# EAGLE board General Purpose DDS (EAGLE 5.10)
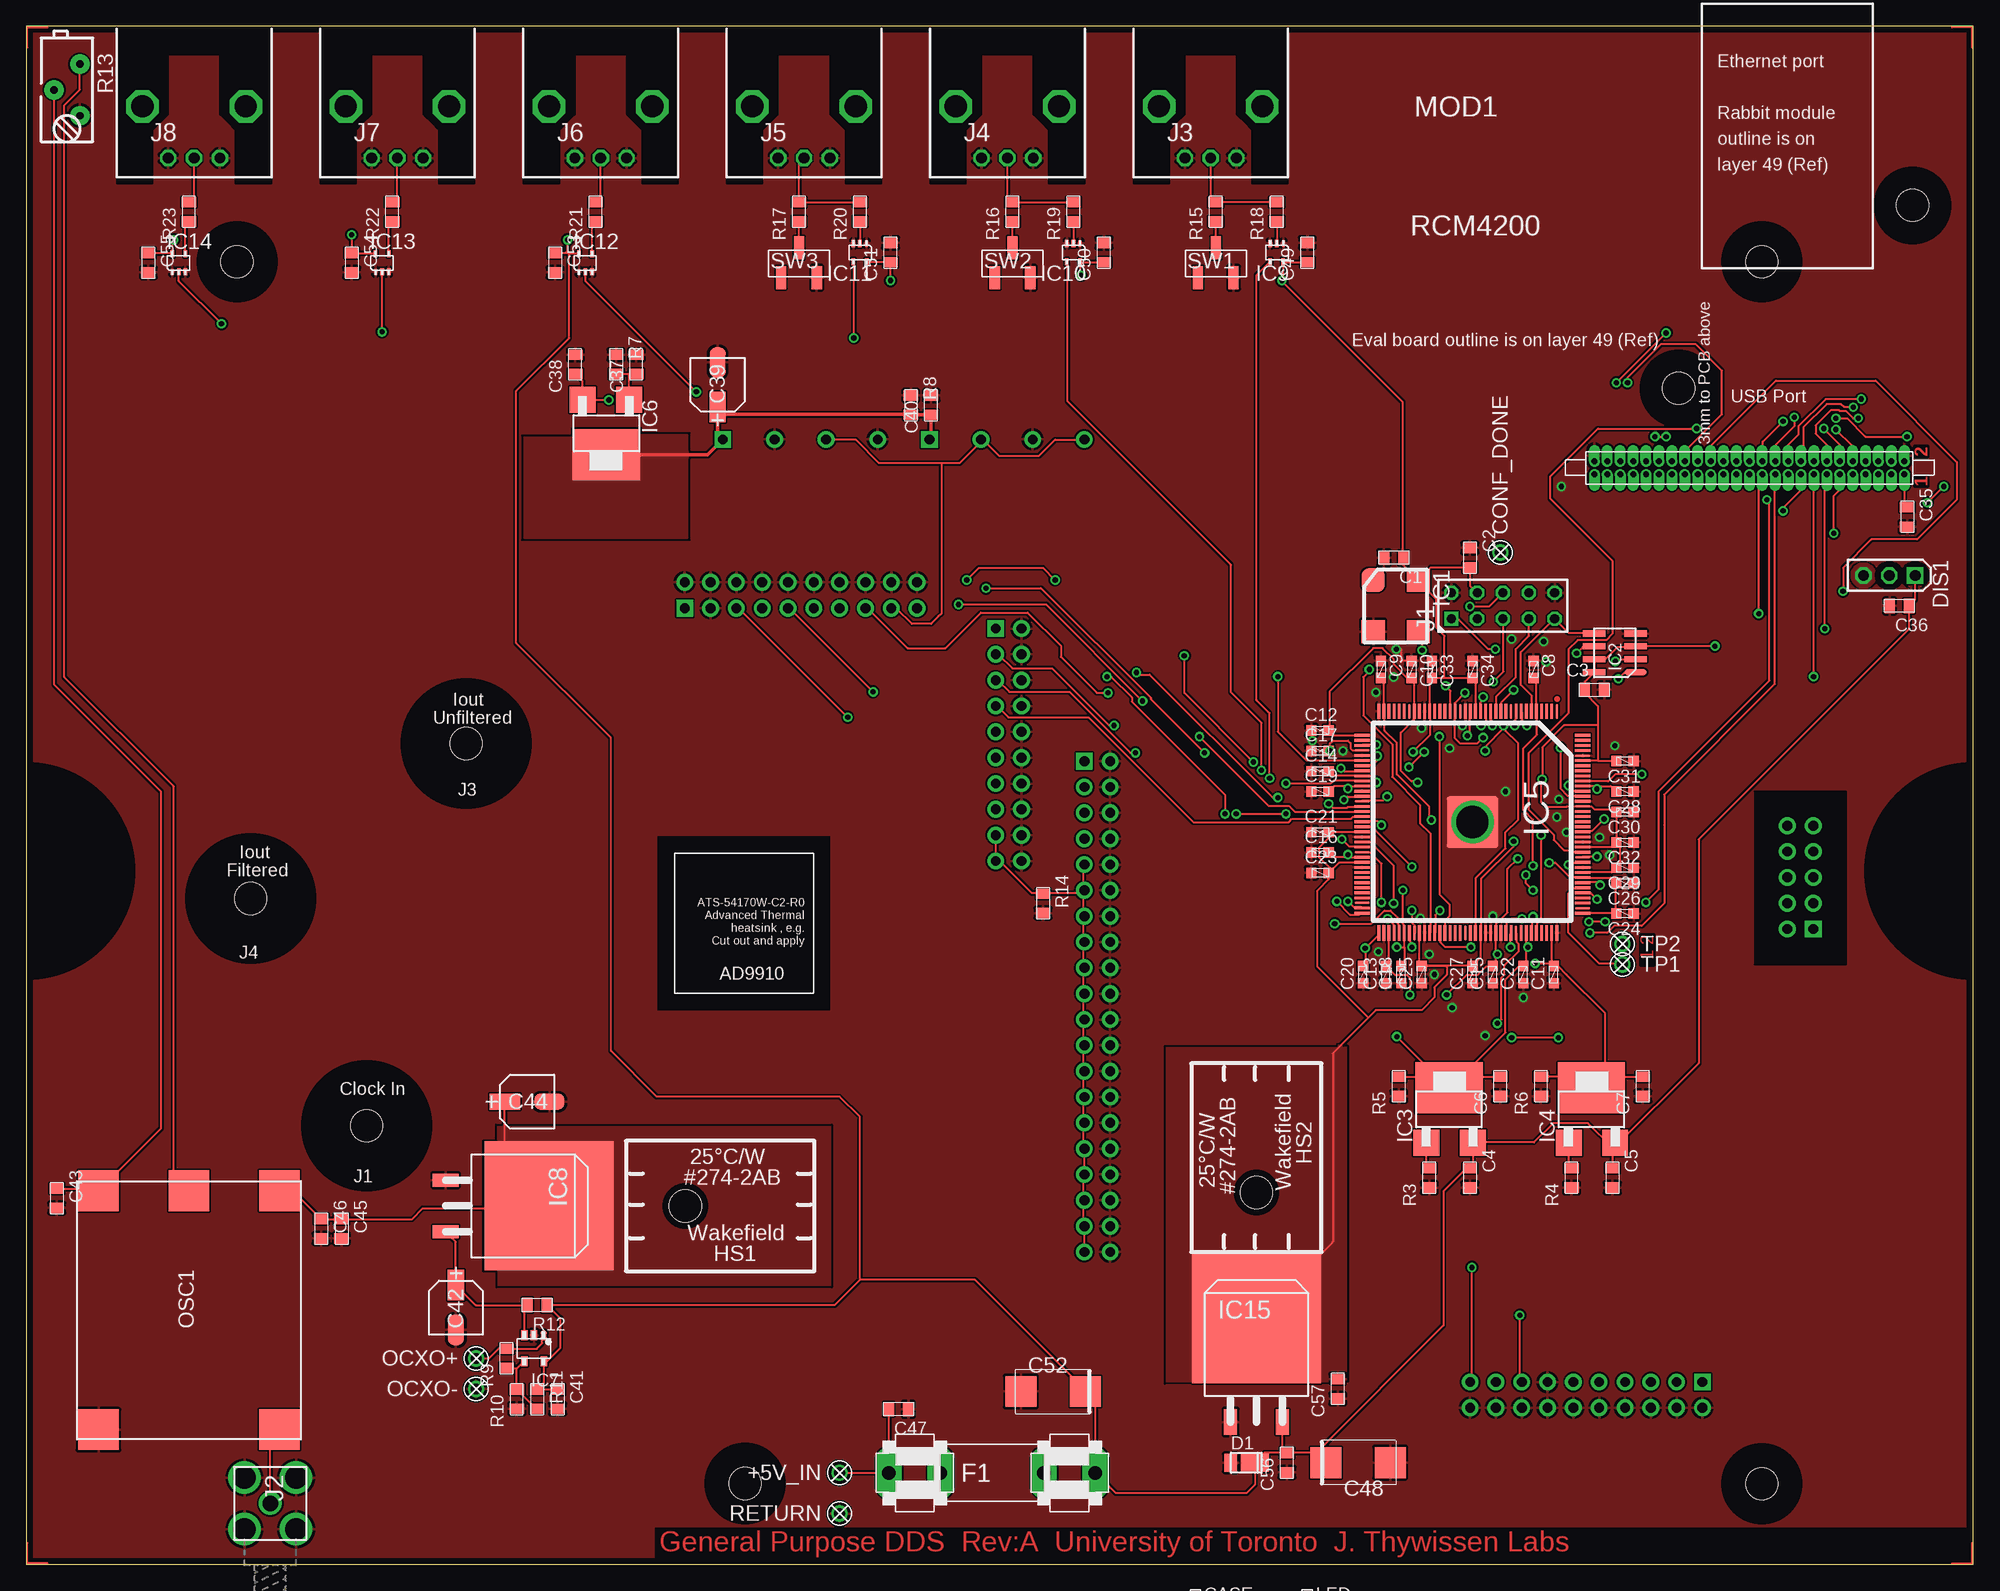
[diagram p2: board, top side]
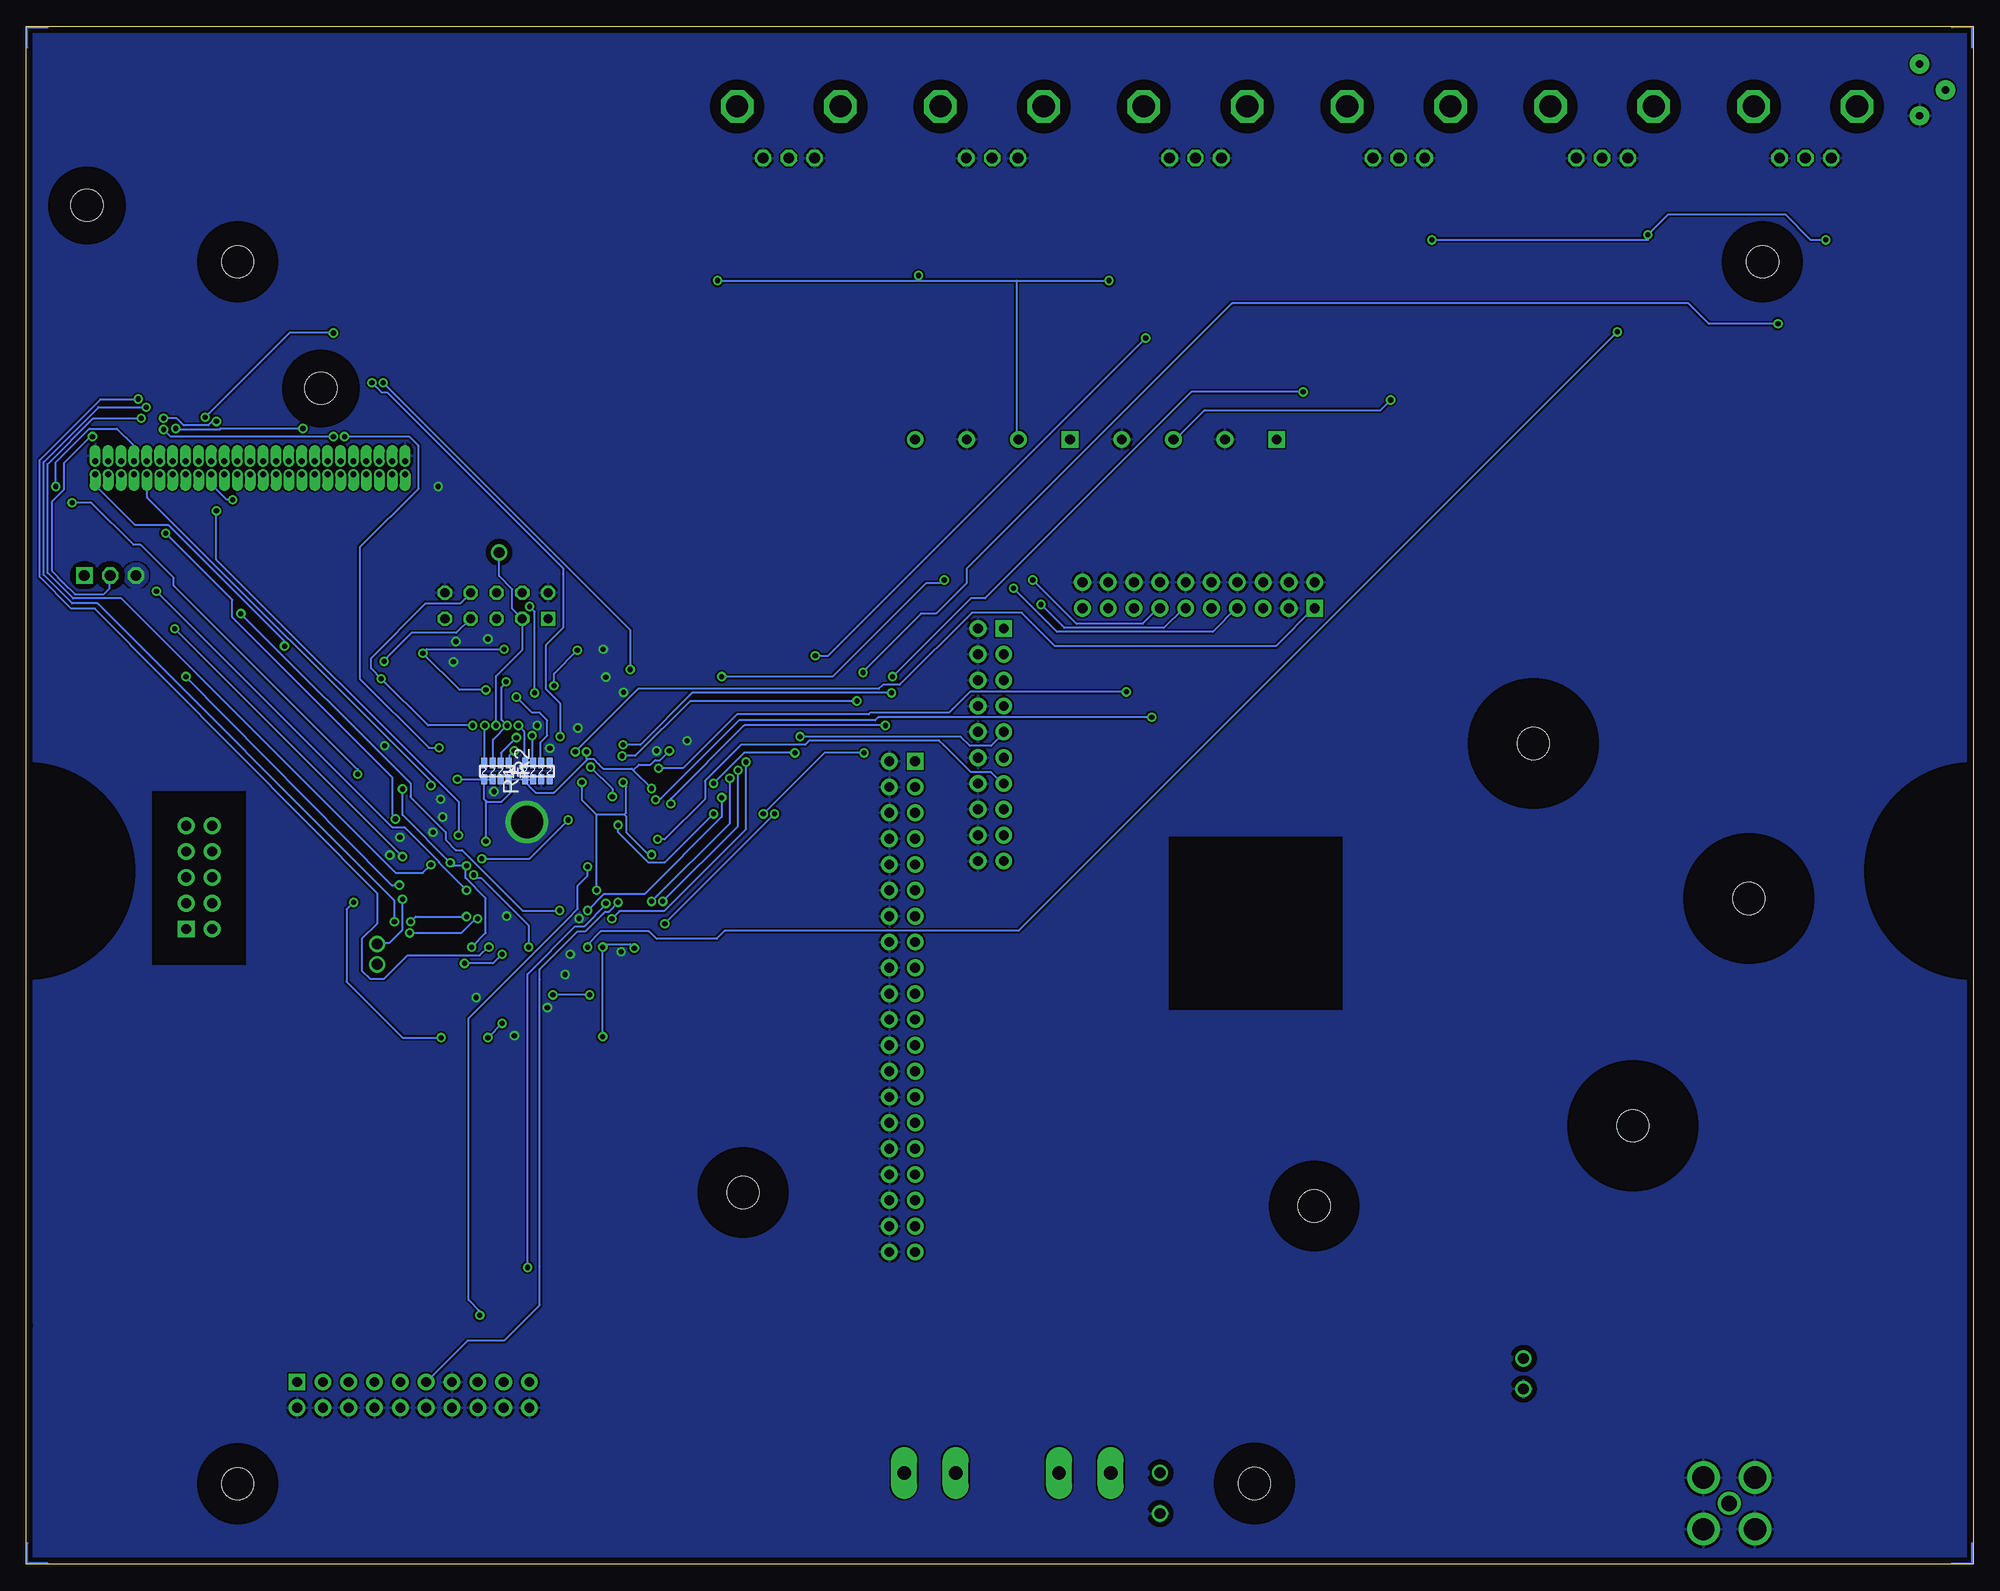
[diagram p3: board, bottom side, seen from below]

Size 191.5 x 151.25 mm. Coordinates in mm from the lower left corner, seen from the top.
Outline: 191.5,23.5 191.5,151.25 0,151.25 0,0 182,0 191.5,0 191.5,23.5
Copper layers (1+16): Top 0.035mm / dielectric 1.5mm / Bottom 0.035mm
Design rules "DRC standard check": minimum track width 7mil, minimum drill 20mil, track to track 7mil, track to pad 7mil, pad to pad 7mil, via to via 7mil, smd to smd 0mil, copper to edge 25mil, drill to drill 8mil, minimum pad ring 10mil, minimum via ring 8mil, stop-mask expansion 4mil, vias tented up to drill 0mil, thermal gap 10mil
Net classes: 0 default: width 0.178 mm, drill 0.508 mm, clearance 0.178 mm; 1 Power: width 0.356 mm, drill 0.711 mm, clearance 0.178 mm
Holes 3.17 mm at 20.71,128.09 170.72,128.1 170.72,7.94 70.71,7.96
tRestrict: area -10.7,57.5 to 10.7,78.9; area 180.8,57.5 to 202.2,78.9; area 16.9,124.3 to 24.5,131.9; area 166.9,124.3 to 174.5,131.9; area 166.9,4.1 to 174.5,11.7; area 66.9,4.1 to 74.5,11.8; 29 lines
bRestrict: area -10.7,57.5 to 10.7,78.9; area 180.8,57.5 to 202.2,78.9; area 16.9,124.3 to 24.5,131.9; area 166.9,124.3 to 174.5,131.9; area 166.9,4.1 to 174.5,11.7; area 66.9,4.1 to 74.5,11.8; 6 lines

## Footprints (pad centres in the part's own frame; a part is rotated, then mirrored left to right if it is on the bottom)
TP-0.042B = drill 1.067 round: TP 0,0
2012(0805) = smd 1.016 x 1.397: 1 -0.953,0; 2 0.953,0
1608(0603) = smd 1.016 x 1.016: 1 -0.85,0; 2 0.85,0
CAP:NIPPONCHEM_E61 = smd 3 x 1.6: NEG -2.2,0; POS 2.2,0
EIA-7343 = smd 3.048 x 3.048: + 3.175,0; - -3.175,0
ZENER:DFLZ_V_(1W) = smd 1.25 x 1.75: A -1.525,0 | smd 2.75 x 1.75: C 0.85,0
DDS:AD9910,EVALBOARD = drill 0.965 pad 1.651 square: P1.1 74.5,46.75; TB1.1 89.74,15.104; TB2.1 110.06,15.104; U5.1 113.806,31.701; U6.1 83.208,33.702; U8.1 2.807,63.254; U9.1 13.697,107.8 | drill 0.965 pad 1.651 round: P1.2 71.96,46.75; P1.3 74.5,49.29; P1.4 71.96,49.29; P1.5 74.5,51.83; P1.6 71.96,51.83; P1.7 74.5,54.37; P1.8 71.96,54.37; P1.9 74.5,56.91; P1.10 71.96,56.91; P1.11 74.5,59.45; P1.12 71.96,59.45; P1.13 74.5,61.99; P1.14 71.96,61.99; P1.15 74.5,64.53; P1.16 71.96,64.53; P1.17 74.5,67.07; P1.18 71.96,67.07; P1.19 74.5,69.61; P1.20 71.96,69.61; P1.21 74.5,72.15; P1.22 71.96,72.15; P1.23 74.5,74.69; P1.24 71.96,74.69; P1.25 74.5,77.23; P1.26 71.96,77.23; P1.27 74.5,79.77; P1.28 71.96,79.77; P1.29 74.5,82.31; P1.30 71.96,82.31; P1.31 74.5,84.85; P1.32 71.96,84.85; P1.33 74.5,87.39; P1.34 71.96,87.39; P1.35 74.5,89.93; P1.36 71.96,89.93; P1.37 74.5,92.47; P1.38 71.96,92.47; P1.39 74.5,95.01; P1.40 71.96,95.01; TB1.2 84.66,15.104; TB1.3 79.58,15.104; TB1.4 74.5,15.104; TB2.2 104.98,15.104; TB2.3 99.9,15.104; TB2.4 94.82,15.104; U5.2 113.806,29.161; U5.3 111.266,31.701; U5.4 111.266,29.161; U5.5 108.726,31.701; U5.6 108.726,29.161; U5.7 106.186,31.701; U5.8 106.186,29.161; U5.9 103.646,31.701; U5.10 103.646,29.161; U5.11 101.106,31.701; U5.12 101.106,29.161; U5.13 98.566,31.701; U5.14 98.566,29.161; U5.15 96.026,31.701; U5.16 96.026,29.161; U5.17 93.486,31.701; U5.18 93.486,29.161; U5.19 90.946,31.701; U5.20 90.946,29.161; U6.2 80.668,33.702; U6.3 83.208,36.242; U6.4 80.668,36.242; U6.5 83.208,38.782; U6.6 80.668,38.782; U6.7 83.208,41.322; U6.8 80.668,41.322; U6.9 83.208,43.862; U6.10 80.668,43.862; U6.11 83.208,46.402; U6.12 80.668,46.402; U6.13 83.208,48.942; U6.14 80.668,48.942; U6.15 83.208,51.482; U6.16 80.668,51.482; U6.17 83.208,54.022; U6.18 80.668,54.022; U6.19 83.208,56.562; U6.20 80.668,56.562; U8.2 5.347,63.254; U8.3 2.807,60.714; U8.4 5.347,60.714; U8.5 2.807,58.174; U8.6 5.347,58.174; U8.7 2.807,55.634; U8.8 5.347,55.634; U8.9 2.807,53.094; U8.10 5.347,53.094; U9.2 13.697,110.34; U9.3 16.237,107.8; U9.4 16.237,110.34; U9.5 18.777,107.8; U9.6 18.777,110.34; U9.7 21.317,107.8; U9.8 21.317,110.34; U9.9 23.857,107.8; U9.10 23.857,110.34; U9.11 26.397,107.8; U9.12 26.397,110.34; U9.13 28.937,107.8; U9.14 28.937,110.34; U9.15 31.477,107.8; U9.16 31.477,110.34; U9.17 34.017,107.8; U9.18 34.017,110.34; U9.19 36.557,107.8; U9.20 36.557,110.34 | hole 3.175: 135.3,45; 156.5,60.25; 145.1,82.6
DISPLAY:3WIRE = drill 1.067 octagon: COM 0,-2.54; RXD 0,0 | drill 1.067 square: VDD 0,2.54
FUSE = drill 1.321 pad 2.54 long: 1A -10.16,0; 1B -5.08,0; 2A 10.16,0; 2B 5.08,0
HEATSINK:274-2AB(WAKEFIELD,25C/W) = hole 3.175: 3.429,0
CSX750(CITIZEN_OSC) = smd 2.286 x 2.286: 1 -2.54,-1.27; 2 2.54,-1.27; 3 2.54,3.175; 4 -2.54,3.175
SOIC-8@1 = smd 0.6 x 2.2: 1 -1.27,-2.032; 2 0,-2.032; 3 1.27,-2.032; 4 2.54,-2.032; 5 2.54,2.032; 6 1.27,2.032; 7 0,2.032; 8 -1.27,2.032
SOT223(C) = smd 2.54 x 2.54: 1 -2.286,-2.54; 3 2.286,-2.54 | smd 6.6 x 5: 2 -0.05,2.87
EQFP144(TQFP_WITH_GROUND_PAD) = smd 1.5 x 0.27: 1 -10.89,8.29; 2 -10.89,7.79; 3 -10.89,7.29; 4 -10.89,6.79; 5 -10.89,6.29; 6 -10.89,5.79; 7 -10.89,5.29; 8 -10.89,4.79; 9 -10.89,4.29; 10 -10.89,3.79; 11 -10.89,3.29; 12 -10.89,2.79; 13 -10.89,2.29; 14 -10.89,1.79; 15 -10.89,1.29; 16 -10.89,0.79; 17 -10.89,0.29; 18 -10.89,-0.21; 19 -10.89,-0.71; 20 -10.89,-1.21; 21 -10.89,-1.71; 22 -10.89,-2.21; 23 -10.89,-2.71; 24 -10.89,-3.21; 25 -10.89,-3.71; 26 -10.89,-4.21; 27 -10.89,-4.71; 28 -10.89,-5.21; 29 -10.89,-5.71; 30 -10.89,-6.21; 31 -10.89,-6.71; 32 -10.89,-7.21; 33 -10.89,-7.71; 34 -10.89,-8.21; 35 -10.89,-8.71; 36 -10.89,-9.21; 73 10.91,-9.21; 74 10.91,-8.71; 75 10.91,-8.21; 76 10.91,-7.71; 77 10.91,-7.21; 78 10.91,-6.71; 79 10.91,-6.21; 80 10.91,-5.71; 81 10.91,-5.21; 82 10.91,-4.71; 83 10.91,-4.21; 84 10.91,-3.71; 85 10.91,-3.21; 86 10.91,-2.71; 87 10.91,-2.21; 88 10.91,-1.71; 89 10.91,-1.21; 90 10.91,-0.71; 91 10.91,-0.21; 92 10.91,0.29; 93 10.91,0.79; 94 10.91,1.29; 95 10.91,1.79; 96 10.91,2.29; 97 10.91,2.79; 98 10.91,3.29; 99 10.91,3.79; 100 10.91,4.29; 101 10.91,4.79; 102 10.91,5.29; 103 10.91,5.79; 104 10.91,6.29; 105 10.91,6.79; 106 10.91,7.29; 107 10.91,7.79; 108 10.91,8.29 | smd 0.27 x 1.5: 37 -8.54,-10.86; 38 -8.04,-10.86; 39 -7.54,-10.86; 40 -7.04,-10.86; 41 -6.54,-10.86; 42 -6.04,-10.86; 43 -5.54,-10.86; 44 -5.04,-10.86; 45 -4.54,-10.86; 46 -4.04,-10.86; 47 -3.54,-10.86; 48 -3.04,-10.86; 49 -2.54,-10.86; 50 -2.04,-10.86; 51 -1.54,-10.86; 52 -1.04,-10.86; 53 -0.54,-10.86; 54 -0.04,-10.86; 55 0.46,-10.86; 56 0.96,-10.86; 57 1.46,-10.86; 58 1.96,-10.86; 59 2.46,-10.86; 60 2.96,-10.86; 61 3.46,-10.86; 62 3.96,-10.86; 63 4.46,-10.86; 64 4.96,-10.86; 65 5.46,-10.86; 66 5.96,-10.86; 67 6.46,-10.86; 68 6.96,-10.86; 69 7.46,-10.86; 70 7.96,-10.86; 71 8.46,-10.86; 72 8.96,-10.86; 109 8.96,10.84; 110 8.46,10.84; 111 7.96,10.84; 112 7.46,10.84; 113 6.96,10.84; 114 6.46,10.84; 115 5.96,10.84; 116 5.46,10.84; 117 4.96,10.84; 118 4.46,10.84; 119 3.96,10.84; 120 3.46,10.84; 121 2.96,10.84; 122 2.46,10.84; 123 1.96,10.84; 124 1.46,10.84; 125 0.96,10.84; 126 0.46,10.84; 127 -0.04,10.84; 128 -0.54,10.84; 129 -1.04,10.84; 130 -1.54,10.84; 131 -2.04,10.84; 132 -2.54,10.84; 133 -3.04,10.84; 134 -3.54,10.84; 135 -4.04,10.84; 136 -4.54,10.84; 137 -5.04,10.84; 138 -5.54,10.84; 139 -6.04,10.84; 140 -6.54,10.84; 141 -7.04,10.84; 142 -7.54,10.84; 143 -8.04,10.84; 144 -8.54,10.84 | smd 5.08 x 5.08: PAD 0,0
SOT23-5 = smd 0.635 x 0.991: 1 -0.635,-1.27; 2 0.318,-1.27; 3 1.27,-1.27; 4 1.27,1.27; 5 -0.635,1.27
TO263 = smd 1.27 x 2.54: 1 -2.54,0; 3 2.54,0 | smd 12.7 x 12.7: 2 0,10.16
SOT353 = smd 0.35 x 0.7: 1 -0.65,-0.9; 2 0,-0.9; 3 0.65,-0.9; 4 0.65,0.9; 5 -0.65,0.9
CONN-2X5-BLASTER = drill 0.889 square: 1 0,5.08 | drill 0.889 octagon: 2 2.54,5.08; 3 0,2.54; 4 2.54,2.54; 5 0,0; 6 2.54,0; 7 0,-2.54; 8 2.54,-2.54; 9 0,-5.08; 10 2.54,-5.08
CONN:SMA1 = drill 2.184 round: COM1 -2.54,-2.54; COM2 -2.54,2.54; COM3 2.54,2.54; COM4 2.54,-2.54 | drill 1.511 round: CONDUCTOR 0,0
CONN-BNC-AMP-TYPE3HORIZ = drill 1.067 octagon: CONDUCTOR 0,-12.7; SHIELD1 -2.54,-12.7; SHIELD2 2.54,-12.7 | drill 2.184 octagon: P$1 -5.08,-7.62; P$2 5.08,-7.62
RABBIT_RCM42XX(THRU) = drill 0.584 pad 1.016 offset: 1 55.225,3.193; 2 55.225,4.463; 3 53.955,3.193; 4 53.955,4.463; 5 52.685,3.193; 6 52.685,4.463; 7 51.415,3.193; 8 51.415,4.463; 9 50.145,3.193; 10 50.145,4.463; 11 48.875,3.193; 12 48.875,4.463; 13 47.605,3.193; 14 47.605,4.463; 15 46.335,3.193; 16 46.335,4.463; 17 45.065,3.193; 18 45.065,4.463; 19 43.795,3.193; 20 43.795,4.463; 21 42.525,3.193; 22 42.525,4.463; 23 41.255,3.193; 24 41.255,4.463; 25 39.985,3.193; 26 39.985,4.463; 27 38.715,3.193; 28 38.715,4.463; 29 37.445,3.193; 30 37.445,4.463; 31 36.175,3.193; 32 36.175,4.463; 33 34.905,3.193; 34 34.905,4.463; 35 33.635,3.193; 36 33.635,4.463; 37 32.365,3.193; 38 32.365,4.463; 39 31.095,3.193; 40 31.095,4.463; 41 29.825,3.193; 42 29.825,4.463; 43 28.555,3.193; 44 28.555,4.463; 45 27.285,3.193; 46 27.285,4.463; 47 26.015,3.193; 48 26.015,4.463; 49 24.745,3.193; 50 24.745,4.463 | hole 3.175: 56.02,29.654; 33.02,11.654
OSCILLATOR:AOCJY(ABRACON-OCXO) = smd 4 x 4: COM 11.75,-8.9; CTRL -11.75,-8.9; OUT 11.75,8.9; VDD -11.75,8.9; VREF -11.75,0
PANASONIC_EXB-V8V(QUAD-R-PACK) = smd 1 x 0.59: 1A -0.8,1.2; 1B 0.8,1.2; 2A -0.8,0.4; 2B 0.8,0.4; 3A -0.8,-0.4; 3B 0.8,-0.4; 4A -0.8,-1.2; 4B 0.8,-1.2
BOURNS:3296Y = drill 0.711 pad 1.905 round: CCW 2.54,1.27; CW -2.54,1.27; W 0,-1.27
SWITCH:SPDT-DIP(COPAL) = smd 1 x 2.25: 1 -1.75,-1.475; 2 1.75,-1.475; COM 0,1.475

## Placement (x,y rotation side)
+5V_IN  [TP-0.042B]  80,9 180 top
C1  0.1uF  [2012(0805)]  134.5,99 180 top
C2  0.1uF  [2012(0805)]  142,99 270 top
C3  0.1uF  [2012(0805)]  154.25,86 0 top
C4  0.1uF  [2012(0805)]  142,38 270 top
C5  0.1uF  [2012(0805)]  156,38 270 top
C6  0.1uF  [2012(0805)]  145,47 90 top
C7  0.1uF  [2012(0805)]  159,47 90 top
C8  0.1uF  [1608(0603)]  148.25,88 270 top
C9  0.1uF  [1608(0603)]  133.25,88 270 top
C10  0.1uF  [1608(0603)]  136.25,88 270 top
C11  0.1uF  [1608(0603)]  150.25,58 90 top
C12  0.1uF  [1608(0603)]  127.25,82 0 top
C13  0.1uF  [1608(0603)]  133.75,58 90 top
C14  0.1uF  [1608(0603)]  127.25,78 0 top
C15  0.1uF  [1608(0603)]  144.25,58 90 top
C16  0.1uF  [1608(0603)]  127.25,70 0 top
C17  0.1uF  [1608(0603)]  127.25,80 0 top
C18  0.1uF  [1608(0603)]  135.25,58 90 top
C19  0.1uF  [1608(0603)]  127.25,76 0 top
C20  0.1uF  [1608(0603)]  131.5,58 90 top
C21  0.1uF  [1608(0603)]  127.25,72 0 top
C22  0.1uF  [1608(0603)]  147.25,58 90 top
C23  0.1uF  [1608(0603)]  127.25,68 0 top
C24  0.1uF  [1608(0603)]  157.25,64 180 top
C25  0.1uF  [1608(0603)]  137.25,58 90 top
C26  0.1uF  [1608(0603)]  157.25,67 180 top
C27  0.1uF  [1608(0603)]  142.25,58 90 top
C28  0.1uF  [1608(0603)]  157.25,76 180 top
C29  0.1uF  [1608(0603)]  157.25,68.5 180 top
C30  0.1uF  [1608(0603)]  157.25,74 180 top
C31  0.1uF  [1608(0603)]  157.25,79 180 top
C32  0.1uF  [1608(0603)]  157.25,71 180 top
C33  0.1uF  [1608(0603)]  138.25,88 270 top
C34  0.1uF  [1608(0603)]  142.25,88 270 top
C35  0.1uF  [2012(0805)]  185,103 270 top
C36  0.1uF  [2012(0805)]  184.25,94.25 180 top
C37  12pF  [2012(0805)]  60,118 90 top
C38  0.1uF  [2012(0805)]  54,118 90 top
C39  39uF  [CAP:NIPPONCHEM_E61]  68,116 270 top
C40  0.1uF  [2012(0805)]  89,114 90 top
C41  0.1uF  [2012(0805)]  52.25,16.25 270 top
C42  39uF  [CAP:NIPPONCHEM_E61]  42.25,25.25 90 top
C43  10nF  [2012(0805)]  3,36 270 top
C44  39uF  [CAP:NIPPONCHEM_E61]  49.25,45.5 180 top
C45  10nF  [2012(0805)]  31,33 270 top
C46  0.1uF  [2012(0805)]  29,33 270 top
C47  0.1uF  [2012(0805)]  85.8,15.26 180 top
C48  10uF  [EIA-7343]  131,10 180 top
C49  0.1uF  [2012(0805)]  126,129 90 top
C50  0.1uF  [2012(0805)]  106,129 90 top
C51  0.1uF  [2012(0805)]  85,129 90 top
C52  10uF  [EIA-7343]  101,17 0 top
C53  0.1uF  [2012(0805)]  52,128 270 top
C54  0.1uF  [2012(0805)]  32,128 270 top
C55  0.1uF  [2012(0805)]  12,128 270 top
C56  0.1uF  [2012(0805)]  124,10 90 top
C57  0.1uF  [2012(0805)]  129,17.25 90 top
CASE  1598D  [MISC]  115,-3 0 top
CBL1  A-MCU60005-R  [MISC]  not placed on the board
COAX  SMA-SMA coax  [MISC]  not placed on the board
COAX1  SMA-SMA coax  [MISC]  not placed on the board
CON1  555052-1  [MISC]  not placed on the board
CONF_DONE  [TP-0.042B]  145,99.5 90 top
CONN  SMA-SMA bulkhead  [MISC]  not placed on the board
D1  DFLZ5V6-7  [ZENER:DFLZ_V_(1W)]  120,10 0 top
DDS1  [DDS:AD9910,EVALBOARD]  178.57,125.73 180 top
DIS1  NHD-0216B3Z-FL-GBW  [DISPLAY:3WIRE]  183.25,97.25 270 top
F1  2A  [FUSE]  95,9 0 top
HS1  274-2AB  [HEATSINK:274-2AB(WAKEFIELD,25C/W)]  68.25,35.25 180 top
HS2  274-2AB  [HEATSINK:274-2AB(WAKEFIELD,25C/W)]  121,40 270 top
HTSNK  [MISC]  not placed on the board
IC1  100MHz  [CSX750(CITIZEN_OSC)]  133.75,94.25 270 top
IC2  EPCS4  [SOIC-8@1]  156.25,89 90 top
IC3  LT3080EST  [SOT223(C)]  140,44 0 top
IC4  LT3080EST  [SOT223(C)]  154,44 0 top
IC5  EP3C10E144C7  [EQFP144(TQFP_WITH_GROUND_PAD)]  142.25,73 270 top
IC6  LT3080EST  [SOT223(C)]  57,112 180 top
IC7  AD8605ART  [SOT23-5]  50.25,21.25 180 top
IC8  LM1086CS-3.3  [TO263]  41.25,35.25 270 top
IC9  NL17SZ125DFT2G  [SOT353]  123,129 180 top
IC10  NL17SZ125DFT2G  [SOT353]  103,129 180 top
IC11  NL17SZ125DFT2G  [SOT353]  82,129 180 top
IC12  NL17SZ125DFT2G  [SOT353]  55,128 0 top
IC13  NL17SZ125DFT2G  [SOT353]  35,128 0 top
IC14  NL17SZ125DFT2G  [SOT353]  15,128 0 top
IC15  LM1086CS-3.3  [TO263]  121,14 0 top
J1  [CONN-2X5-BLASTER]  145.25,93 90 top
J2  Amphenol 132134  [CONN:SMA1]  24,6 270 top
J3  227677-1  [CONN-BNC-AMP-TYPE3HORIZ]  116.5,151 0 top
J4  227677-1  [CONN-BNC-AMP-TYPE3HORIZ]  96.5,151 0 top
J5  227677-1  [CONN-BNC-AMP-TYPE3HORIZ]  76.5,151 0 top
J6  227677-1  [CONN-BNC-AMP-TYPE3HORIZ]  56.5,151 0 top
J7  227677-1  [CONN-BNC-AMP-TYPE3HORIZ]  36.5,151 0 top
J8  227677-1  [CONN-BNC-AMP-TYPE3HORIZ]  16.5,151 0 top
LED  OCXO LED  [MISC]  126,-3 0 top
MOD1  RCM4200  [RABBIT_RCM42XX(THRU)]  129.5,104 0 top
OCXO+  [TP-0.042B]  44.25,20.25 180 top
OCXO-  [TP-0.042B]  44.25,17.25 180 top
OSC1  AOCJY-20.000MHZ-E  [OSCILLATOR:AOCJY(ABRACON-OCXO)]  16,25 270 top
P1  [MISC]  not placed on the board
R1  1K  [PANASONIC_EXB-V8V(QUAD-R-PACK)]  141.25,78 90 bottom
R2  10K  [PANASONIC_EXB-V8V(QUAD-R-PACK)]  145.25,78 270 bottom
R3  121K  [2012(0805)]  138,38 90 top
R4  249K  [2012(0805)]  152,38 90 top
R5  1K  [2012(0805)]  135,47 90 top
R6  1K  [2012(0805)]  149,47 90 top
R7  182K  [2012(0805)]  58,118 270 top
R8  1K  [2012(0805)]  87,114 270 top
R9  30.1K  [2012(0805)]  47.25,20.25 90 top
R10  12.1K  [2012(0805)]  48.25,16.25 90 top
R11  121  [2012(0805)]  50.25,16.25 270 top
R12  0.1  [2012(0805)]  50.25,25.5 180 top
R13  3296Z-10K  [BOURNS:3296Y]  4,145 270 top
R14  10K  [2012(0805)]  100,65 270 top
R15  49.9  [2012(0805)]  117,133 90 top
R16  49.9  [2012(0805)]  97,133 90 top
R17  49.9  [2012(0805)]  76,133 90 top
R18  121  [2012(0805)]  123,133 90 top
R19  121  [2012(0805)]  103,133 90 top
R20  121  [2012(0805)]  82,133 90 top
R21  49.9  [2012(0805)]  56,133 90 top
R22  49.9  [2012(0805)]  36,133 90 top
R23  49.9  [2012(0805)]  16,133 90 top
RETURN  [TP-0.042B]  80,5 180 top
SW1  CJS-1200TA  [SWITCH:SPDT-DIP(COPAL)]  117,128 0 top
SW2  CJS-1200TA  [SWITCH:SPDT-DIP(COPAL)]  97,128 0 top
SW3  CJS-1200TA  [SWITCH:SPDT-DIP(COPAL)]  76,128 0 top
TB1  [MISC]  not placed on the board
TB2  [MISC]  not placed on the board
TP1  [TP-0.042B]  157,59 0 top
TP2  [TP-0.042B]  157,61 0 top
U5  [MISC]  not placed on the board
U6  [MISC]  not placed on the board
U9  [MISC]  not placed on the board
U$20  [TITLEBLOCK_PCB]  0,-1.25 0 top
U$21  [CASE:HAMMOND_1598D]  0,151.25 270 top

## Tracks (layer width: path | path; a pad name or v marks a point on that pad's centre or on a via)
+1.2V  (via drill 0.51)
  Top 0.178: v132.8,76.9 132.2,77.5 131.4,77.5 IC5.45 | v130,69.8 130,69.54 | C10.2 136.2,87.2 135.8,87.2 134.5,88.5 134.5,89 133.4,90.1 132.5,90.1 128.2,85.8 128.2,82 C12.2 | 135.2,78.1 135.2,81.8 136.5,83.1 136.5,83.8 IC5.29 | v148.2,68.7 148.2,73.25 | v149.8,69 150.4,69 151.8,67.6 153,67.6 IC5.116 | 148.6,83.8 IC5.5 | C24.2 156.3,64.1 156.3,67 C26.2 | v154.5,76.25 154.5,76.54 | v134.8,60.7 135.54,60.7 | v134.8,51.9 138.7,48 IC3.2 141.2,48 145.5,52.3 145.5,57.5 146.8,58.8 147.2,58.8 C22.2 | 147.54,60.7 v147.7,60.7 | v135.4,66.3 135.4,63 135.5,62.9 135.5,62.1 IC5.78
  Top 0.18: IC5.5 148.54,86.86 C8.2 | IC5.29 136.54,86.86 C10.2 | IC5.37 128.56,81.54 C12.2 | IC5.45 128.56,77.54 C14.2 | IC5.61 130,69.54 128.56,69.54 C16.2 | IC5.78 135.54,60.7 135.54,59.14 C18.2 | IC5.102 147.54,60.7 147.54,59.14 C22.2 | IC5.109 156.36,64.04 C24.2 | IC5.116 155.86,67.54 C26.2 | IC5.134 154.5,76.54 155.86,76.54 C28.2 | R5.2 138.87,47.95 IC3.2 141.03,47.95 C6.2 | 148.6,83.8 148.6,81.6 147.25,80.25 147.25,74.2 148.2,73.25 | 135.2,78.1 135.2,78.05 136.25,77 136.75,77 v136.85,76.9 | IC5.73 133.04,61.94 v131.7,60.6 131.7,59.4 C20.2
  Bottom 0.178: 148.3,68.7 149.5,68.7 v149.8,69 154.5,73.7 v154.5,76.25 | 134.7,60.6 v134.8,60.7 v134.8,51.9 | 148.3,68.7 148.3,67.5 146.3,65.5 146.3,62.1 v147.7,60.7 | 148.3,68.7 v148.2,68.7 | v135.4,66.3 135.4,73.7 135.4,73.75
  Bottom 0.18: 134.7,60.6 134.7,60.8 134.5,61 132.1,61 v131.7,60.6 | v132.8,76.9 132.8,76.8 132.5,76.5 132.5,73.9 132.65,73.75 | v130,69.8 130.3,69.8 132.5,72 132.5,73.55 132.65,73.7 132.65,73.75 | 135.4,73.7 136.85,75.15 v136.85,76.9 | 135.4,73.75 132.65,73.75
+1.8V
  Top 0.356: R8.2 87,113.1 68,113.1 C39.POS
  Top 0.36: 68,113.1 68,111.14 DDS1.TB2.1 67.01,109.13 IC6.2 | R8.2 C40.1 89,110.8 DDS1.TB1.1
  pour Top (no thermals): 49,111 65,111 65,101 49,101
+2.5V  (via drill 0.51)
  Top 0.178: 151.5,58 150.7,58.8 150.3,58.8 C11.2 150,59.1 v148.4,59.1 | IC4.2 151.5,48 | v136.1,56 136.1,57.7 135.8,58 134.6,58 C13.2 | v139.7,56 141.7,58 142.8,58 143.6,58.8 144.2,58.8 C15.2 | 134.8,78.35 134.8,80.8 133.6,82 133.6,83.8 IC5.35 | 145.7,64.1 144.6,63 144.6,62.1 IC5.96 | 144.54,60 v144.7,60
  Top 0.18: IC5.35 133.54,86.86 C9.2 | IC5.75 134.04,59.14 C13.2 | IC5.96 144.54,60 144.54,59.14 C15.2 | IC5.107 150.04,59.06 C11.2 | R6.2 152.87,47.95 IC4.2 155.03,47.95 155.25,47.95 | 155.25,47.95 C7.2 | 134.8,78.35 134.8,77.7 138,74.5 138,73.4 v138.2,73.2 | 151.5,58 155.25,54.25 155.25,47.95 | 145.7,64.1 145.7,68.4 v146.7,69.4
  Bottom 0.178: v136.1,56 v139.7,56 | v138.2,73.2 142,69.4 v146.7,69.4 | v148.4,59.1 145.6,59.1 v144.7,60
+3.3V  (via drill 0.51)
  Top 0.178: v57.3,114.5 54.8,114.5 IC6.3 | 89.7,93.2 89,92.5 87.1,92.5 85.6,94 85.1,94 DDS1.U5.17 | 93.9,110.4 93.9,110.6 DDS1.TB1.2 94,110.7 95.7,109 99.6,109 101.2,110.6 104,110.6 DDS1.TB1.4 | 91.7,108.3 90,108.3 83.9,108.3 81.6,110.6 78.7,110.6 DDS1.TB2.3 | C21.2 128.1,71.4 127.2,70.5 127.2,69.5 128.4,68.3 | 139.5,87.2 142.2,87.2 C34.2 | 139.5,87.2 138.3,87.2 C33.2 | 139.5,87.2 139.5,91.3 138.7,92.1 138.7,94.9 136.9,96.7 IC1.4 | v130,76.3 130,76.54 | v136.4,79.9 138.1,81.6 138.1,83.8 IC5.26 | 143.1,67.4 143.1,62.1 IC5.93 | C30.2 C32.2 | IC2.7 155.3,89 156.5,90.2 158.2,90.2 IC2.3 158.3,90.3 v166.1,90.3 | 154.6,79.04 154.6,82.5 154.6,84.4 153.3,85.7 C3.1 | v123.5,126.25 123.5,126.2 135.4,114.3 135.4,99 C1.1
  Top 0.18: IC11.5 82.7,128.05 C51.1 v85,126.25 | 103.7,128.05 C50.1 | 103.7,128.05 IC10.5 | C49.1 123.7,128.05 IC9.5 123.65,126.4 v123.5,126.25 | IC6.3 54.71,116.33 C38.1 | 103.7,128.05 103.7,126.8 v103.75,126.75 | C1.1 135.45,98.26 IC1.4 138.18,98.05 C2.2 142,96.25 J1.4 | C3.1 153.3,86.81 IC2.8 IC2.7 | IC5.17 142.54,86.86 C34.2 | IC5.26 138.04,86.94 C33.2 | C17.2 128.14,80.04 128.21,80.04 v128.25,80 128.25,80.75 128.5,81 130,81 130.25,80.75 130.25,80.25 130.46,80.04 IC5.40 | IC5.47 130,76.54 128.64,76.54 C19.2 | IC5.56 128.14,72.04 C21.2 | IC5.62 129.14,69.04 128.4,68.3 C23.2 128.1,67.35 127,66.25 127,58.75 132,53.75 | IC5.81 137.04,59.06 C25.2 | IC5.93 143.04,59.64 C27.2 C25.2 | IC5.122 155.94,70.54 C32.2 156.75,70.65 156.75,69 156.4,68.65 C29.2 155.94,68.04 IC5.117 | IC5.139 154.6,79.04 156.36,79.04 C31.2 | MOD1.1 184.72,104.23 C35.1 | C25.2 139.54,58.85 arc-45 139.72,58.78 139.75,58.75 139.75,58.1 arc-45 139.68,57.93 138.5,56.75 138.5,55.75 137.25,54.5 132.75,54.5 132,53.75 | IC15.2 128.43,31.59 arc45 128.5,31.77 128.5,50.25 132,53.75 | 154.6,82.5 151.25,82.5 149.1,80.35 v149.1,77.2 149,77.1 149,75 149.5,74.5 151.5,74.5 151.54,74.54 IC5.130 153.96,74.54 154.25,74.25 156.15,74.25 C30.2 | 89.7,93.2 90,93.5 90,108.3 | 93.9,110.4 91.8,108.3 91.7,108.3 | 143.1,67.4 146.3,70.6 v146.3,71.1
  Bottom 0.178: 75.6,113.5 78.4,110.7 78.6,110.7 DDS1.TB2.3 | 94.1,126.25 94.1,110.8 94,110.7 DDS1.TB1.2 | R1.1A R1.2A | 142.7,77.2 143.9,77.2 R2.1B 144,77.2 | 142.7,77.2 R1.1A | 145.6,77.2 R2.3B R2.4B v149.1,77.2 | 135.2,78.7 135.7,79.2 136.3,79.2 136.35,79.15 | 136.35,79.15 139.6,75.9 141.4,75.9 142.7,77.2 | R1.1A 142.5,77.2 | v136.4,79.9 136.4,79.2 136.35,79.15 | 146.3,75.1 v146.3,71.1 | v166.1,90.3 166.1,90.8 177.5,102.2 180.8,102.2 184.7,106.1 184.7,107.1 MOD1.1
  Bottom 0.18: v85,126.25 94.1,126.25 103.75,126.25 | v123.5,126.25 103.75,126.25 | 103.75,126.25 v103.75,126.75 | 143.9,77.2 143.9,75.85 144.75,75 146.2,75 146.3,75.1 146.5,75.3 146.5,77.15 R2.4B | 145.6,77.2 145.6,77.15 | v128.25,80 129.15,79.1 129.65,79.1 130.1,78.65 131.25,78.65 131.8,78.1 | 75.6,113.5 58.3,113.5 v57.3,114.5 | 135.2,78.7 134.75,78.25 131.95,78.25 131.8,78.1 | 131.8,78.1 v130,76.3
  pour Top: 112,51 112,18 130,18 130,51
+5V  (via drill 0.51)
  Top 0.178: IC3.3 142.3,41.5 148.3,41.5 150.2,43.4 153.6,43.4 156,41 IC4.3 156,40.8 164.5,49.3 164.5,71.3 185.2,92 185.2,94.2 C36.1 | 102,19.3 104.3,17 C52.+ | 52.5,24.2 52.55,24.25 | 57.5,54.4 57.5,81.3 48.2,90.6 48.2,115.4 53.4,120.6 53.4,128.95 | C4.1 142,38.9 141.6,38.9 139.4,36.7 139.4,23.5 126.9,11 C48.+
  Top 0.18: C56.2 126.87,10.95 C48.+ | IC15.3 123.54,11.41 C56.2 | C56.2 121.8,10.95 D1.C 120.85,7.85 120,7 107.16,7 F1.2A 105.16,16.02 C52.+ | C41.1 R11.1 50.88,17.84 IC7.5 51.23,19.98 52.5,21.25 52.5,24.2 R12.1 79.5,25.5 82,28 | C55.1 14.3,128.95 IC14.5 14.35,130.1 v14.5,130.25 | IC13.5 34.3,128.95 C54.1 v32,130.75 | 53,128.95 C53.1 | 53,128.95 53.4,128.95 54.3,128.95 IC12.5 | v53.25,130.25 53.25,129.2 53,128.95 | C5.1 156,40.8 156,41 156,41.17 IC4.3 | IC3.3 142.29,39.24 C4.1 | DIS1.VDD 185.79,94.84 C36.1 | 82,28 82,44 80,46 62,46 57.5,50.5 57.5,54.4 | 102,19.3 93.3,28 82,28
  Bottom 0.18: v53.25,130.25 32,130.25 v32,130.75 30,132.75 18.5,132.75 16,130.25 v14.5,130.25
AGND  (via drill 0.51, 3.17)
  Top 0.18: C10.1 135.35,88.85 135.25,88.75 135.25,90 134.75,90.5 | IC5.PAD 143.12,73
  other vias: 151,106 134.5,87.25 134.75,90 138.5,58 138,60 140.25,54.75 143.5,52 147.25,55.75 144.25,63.75 154.75,71.5 151.5,72 137.25,82.25 132.75,85.75 149.5,88.75 146.1,91 149.25,90.75 145.5,76 140,80.25 141.25,82.5 129.5,80 126.5,81 137.12,63.52 133,60.25 155.75,69.75 150.55,73.5 150.75,75.25 156.25,80.5 142.25,73
  pour Top (rank 2): 0,0 61.75,0 61.75,3.75 191.25,3.75 191.5,23.5 191.5,151.25 0,151.25
  pour Bottom (rank 2): 0,0 191.5,0 191.5,23.5 191.5,151.25 0,151.25
CMD0  (via drill 0.51)
  Top 0.178: v149,71.7 149,63.4 148.6,63 148.6,62.1 IC5.104 | v172.8,103.6 172.8,103.9 174.5,105.6 174.5,107.1 MOD1.17
  Bottom 0.178: v149,71.7 149,75 172.8,98.8 v172.8,103.6
CMD1  (via drill 0.51)
  Top 0.178: v148.2,63.7 148.1,63.6 148.1,62.1 IC5.103 | v155.3,63.2 v153.7,63.2 | v179.7,113.8 178.8,113.8 178.5,114.1 177.1,114.1 174.8,111.8 174.8,108.7 174.6,108.5 MOD1.18
  Bottom 0.178: v148.2,63.7 153.2,63.7 v153.7,63.2 | 187,94.5 189.8,97.3 189.8,108.4 184.4,113.8 v179.7,113.8
  Bottom 0.18: 187,94.5 184.5,94.5 155.3,65.3 v155.3,63.2
CMD2  (via drill 0.51)
  Top 0.178: v144.7,53.2 145.1,53.6 145.1,57.7 145.4,58 145.4,58.9 146.8,60.3 146.8,61 146.6,61.2 146.6,62 IC5.100 | v150.7,51.8 v146.1,51.8 | 171.45,86.9 160.55,76
  Top 0.18: 160.55,76 160.55,66.35 v159.3,65.1 | 171.45,86.9 171.45,104.45 v171.2,104.7
  Bottom 0.178: v146.1,51.8 v144.7,53.2 | v150.7,51.8 154.5,51.8 159.3,56.6 | v171.2,104.7 171.8,104.7 173.2,106.1 173.2,107.1 MOD1.19
  Bottom 0.18: v159.3,65.1 160,64.4 160,57.3 159.3,56.6
CMD3  (via drill 0.51)
  Top 0.178: v146,60.7 146,62 IC5.99 | v180.5,114.6 177,114.6 174.3,111.9 174.3,111.1 173.3,110.1 173.3,108.5 MOD1.20
  Bottom 0.178: v146,60.7 146.1,60.7 146.9,59.9 154,59.9 156.3,57.6 157.7,57.6 | 190.2,97.1 190.2,108.6 184.2,114.6 v180.5,114.6
  Bottom 0.18: 157.7,57.6 158.5,58.4 158.5,61.5 157,63 157,66 184.75,94 187.1,94 190.2,97.1
CONF_DONE  (via drill 0.51)
  Top 0.178: v143.5,80 143.5,80.4 145.3,82.2 v145.3,82.5 | 145.5,72 145.5,70.4 142.6,67.5 142.6,62.1 IC5.92
  Top 0.18: 145.5,72 146.75,73.25 146.75,80.75 145.5,82 145.5,82.3 v145.3,82.5
  Bottom 0.178: v143.5,80 144,79.5 144,78.8 R2.1A | v145.3,82.5 145.3,87.35 142.7,89.95 J1.3 | CONF_DONE.TP 145,97.2 143.7,95.9 143.7,94 J1.3 | J1.3
CS  (via drill 0.51)
  Top 0.178: v147.1,63.5 146.1,63.5 145.6,63 145.6,62.1 IC5.98 | v153.8,62.1 155.5,62.1 156.2,62.8 158.9,62.8 161.1,65 161.1,72.7 | 172,86.6 172,107.1 MOD1.21
  Top 0.18: 172,86.6 161.1,75.7 161.1,72.7
  Bottom 0.178: v147.1,63.5 147.3,63.5 148.7,62.1 v153.8,62.1
D0  (via drill 0.51)
  Top 0.178: v158.9,77.7 156.3,77.7 155.6,77 153.1,77 IC5.135 | v187,104.4 v188.6,106
  Bottom 0.178: 158.9,78.2 v158.9,77.7 | 185.1,104.4 v187,104.4 | v188.6,106 188.6,108.4 185.3,111.7 182.6,111.7 181,110.1 181,108.5 MOD1.8
  Bottom 0.18: 185.1,104.4 180.95,100.25 180.25,100.25 177,97 177,96.25 158.95,78.2 158.9,78.2
D1  (via drill 0.51)
  Top 0.178: v151.7,76.6 152.2,76.1 153,76.1 IC5.133
  Bottom 0.178: v151.7,76.6 151.7,77 179.6,104.9 179.6,107.1 MOD1.9
D2  (via drill 0.51)
  Top 0.178: v150.9,80.3 150.9,76.3 151.6,75.6 153,75.6 IC5.132 | v160.2,110.9 v161.3,110.9 | v178,111.6 179.6,110 179.6,108.5 MOD1.10
  Bottom 0.178: 158.7,87.1 158.7,100 152.9,105.8 152.9,110 153.8,110.9 v160.2,110.9 | v161.3,110.9 177.3,110.9 v178,111.6
  Bottom 0.18: 158.7,87.1 151.9,80.3 v150.9,80.3
D3  (via drill 0.51)
  Top 0.178: v155.2,73.3 154,72.1 153.1,72.1 IC5.125 | v177.8,101.4 177.8,105.1 178.3,105.6 178.3,107.1 MOD1.11
  Bottom 0.18: v177.8,101.4 171.25,94.85 171.25,93.15 155.5,77.4 155.5,73.75 155.2,73.45 v155.2,73.3
D4  (via drill 0.51)
  Top 0.178: 152.1,70.1 153,70.1 IC5.121 | 151.7,83.9 151.7,90 152.6,90.9 155.4,90.9 156,91.5 156,98.7 149.9,104.8 149.9,107 154.6,111.7 v164.3,111.7 | v176.8,111.7 178.4,110.1 178.4,108.5 MOD1.12
  Top 0.18: 152.1,70.1 151.95,70.25 151.25,70.25 150.25,71.25 150.25,71.75 147.75,74.25 147.75,79.75 151.7,83.7 151.7,83.9
  Bottom 0.178: v164.3,111.7 172.4,111.7 172.5,111.6 176.7,111.6 v176.8,111.7
D5  (via drill 0.51)
  Top 0.178: v154.5,69.6 153.1,69.6 IC5.120 | v176.9,92 176.9,106.9 177.1,107.1 MOD1.13
  Bottom 0.178: v176.9,92 v154.5,69.6
D6  (via drill 0.51)
  Top 0.178: v151.7,68.8 151.9,69 153,69 IC5.119 | v180.2,112.7 179.7,112.7 179,113.4 178.4,113.4 178.3,113.5 177.5,113.5 176,112 176,111.2 177.1,110.1 177.1,108.5 MOD1.14
  Bottom 0.178: 155.95,68.8 182.15,95 186.9,95 189.4,97.5 189.4,108.2 184.9,112.7 v180.2,112.7
  Bottom 0.18: 155.95,68.8 155.15,68 152.5,68 v151.7,68.8
D7  (via drill 0.51)
  Top 0.178: v154.8,66.8 154.5,67.1 153.1,67.1 IC5.115 | v175.8,87.3 175.8,107.1 MOD1.15
  Bottom 0.178: v175.8,87.3 156,67.25 155.55,66.8 v154.8,66.8
DRCTL  (via drill 0.51)
  Top 0.178: v123.1,87.3 123.1,81.9 125.9,79.1 131.3,79.1 IC5.42
  Top 0.18: v92.5,96.8 93.7,98 100,98 v101.2,96.8
  Bottom 0.178: 112.25,87.3 v123.1,87.3 | v92.5,96.8 88.2,92.5 81.7,92.5 80.1,94.1 DDS1.U5.13
  Bottom 0.18: v101.2,96.8 101.5,96.5 103,96.5 112.2,87.3 112.25,87.3
DRHOLD  (via drill 0.51)
  Top 0.178: v132.9,79.5 132.9,79.1 132.4,78.6 131.4,78.6 IC5.43 | v109.8,84.9 100.3,94.4 v91.7,94.4
  Bottom 0.178: v132.9,79.5 131.6,79.5 126.2,84.9 v109.8,84.9 | v91.7,94.4 89.4,92.1 79.6,92.1 77.7,94 77.5,94 DDS1.U5.11
DROVER  (via drill 0.51)
  Top 0.178: v132.8,80.6 131.4,80.6 IC5.39 | 98.5,93.6 93.9,93.6 90.4,90.1 86.7,90.1 82.8,94 82.6,94 DDS1.U5.15
  Top 0.18: v106.4,85.7 105.3,85.7 101.75,89.25 101.75,90.35 98.5,93.6
  Bottom 0.178: v132.8,80.6 131.1,80.6 126,85.7 v106.4,85.7
IN1  (via drill 0.51)
  Top 0.178: v130,65.2 130.6,64.6 131.3,64.6 IC5.71 | IC9.4 122.3,128.1
  Top 0.18: v122.3,77.3 122.3,83.7 121,85 121,126.75 IC9.4
  Bottom 0.178: v122.3,77.3 122.3,72.9 v130,65.2
IN2  (via drill 0.51)
  Top 0.178: 118.5,98.3 102.4,114.4 102.4,128.1 IC10.4 | v128.9,65.2 130.2,63.9 131.1,63.9 131.3,64.1 IC5.72
  Top 0.18: 118.5,98.3 118.5,85.75 121.5,82.75 v121.5,78.1
  Bottom 0.178: v121.5,78.1 121.5,72.6 v128.9,65.2
IN3  (via drill 0.51)
  Top 0.178: v81.4,120.6 81.4,128.1 IC11.4 | v113.9,89.35 113.9,85.7 v120.7,78.9 | v133.9,63.5 134.5,62.9 134.5,62.1 IC5.76
  Bottom 0.178: v120.7,78.9 120.7,72.3 127.5,65.5
  Bottom 0.18: 127.5,65.5 128.75,64.25 133.15,64.25 v133.9,63.5 | v81.4,120.6 112.65,89.35 v113.9,89.35
IO_RST  (via drill 0.51)
  Top 0.178: v137.5,79.9 v136,78.4 | 131.4,75.1 IC5.50
  Top 0.18: 131.4,75.1 133.45,75.1 v133.85,75.5
  Bottom 0.178: 131.3,86.1 v137.5,79.9 | 105.6,86.5 98.5,93.6 93.6,93.6 90.3,90.3 68.6,90.3 64.8,94.1 DDS1.U5.1
  Bottom 0.18: v133.85,75.5 133.85,76.25 v136,78.4 | 105.6,86.5 107.25,86.5 107.65,86.1 131.3,86.1
IO_UPDATE  (via drill 0.51)
  Top 0.178: v128.1,74.8 128.5,74.4 129.9,74.4 130,74.5 131.3,74.5 IC5.51 | v107,82.5 106.5,82.5 100.9,88.1 97,88.1 95.7,89.4 95.4,89.4 DDS1.U6.3
  Bottom 0.178: v128.1,74.8 128.1,75.3 120.9,82.5 v107,82.5
N$1  (via drill 0.51)
  Top 0.178: IC5.13 144.6,83.9 | J1.7 | v156.3,88.8 156.5,89 IC2.2
  Top 0.18: J1.7 147.8,91.3 146.5,90 146.5,87.25 144.6,85.35 144.6,83.9
  Bottom 0.178: v156.3,88.8 156.4,88.8 153.6,91.6 149.2,91.6 J1.7
N$2  (via drill 0.51)
  Top 0.178: v146.3,86 145.1,84.8 145.1,83.9 IC5.12 | v152.5,89.6 153.1,90.2 154.2,90.2 IC2.6 | v144.5,90 143.8,90 140.8,93 J1.1
  Bottom 0.178: v146.3,86 148.9,86 v152.5,89.6
  Bottom 0.18: v144.5,90 152.1,90 v152.5,89.6
N$3  (via drill 0.51)
  Top 0.178: v147.6,82.5 147.1,83 147.1,83.8 IC5.8 | v156.6,87.1 157.2,87.7 158.2,87.7 IC2.1
  Bottom 0.178: v147.6,82.5 152,82.5 v156.6,87.1 157.6,88.1 157.6,89.1 152.2,94.5 148.8,94.5 147.8,95.5 J1.8
N$4
  Top 0.178: 150.3,93 147,89.7 147,86.5 148.1,85.4 148.1,83.9 IC5.6 | 150.3,93 151.7,91.6 154.2,91.6 IC2.5 | 150.3,93 J1.9
N$5
  Top 0.18: C47.2 F1.1A +5V_IN.TP
N$6  (via drill 0.51)
  Top 0.178: v144.2,82.5 144.2,82.9 144,83.1 144,83.8 IC5.14 | v144.3,86.8 145.3,87.8 145.3,93 J1.5
  Bottom 0.178: R2.3A 145.6,78.8 145.6,81.1 v144.2,82.5 144.3,82.5
  Bottom 0.18: v144.3,86.8 144.3,86.7 144.75,86.25 144.75,83.05 v144.2,82.5
N$7  (via drill 0.51)
  Top 0.178: 140.5,83.8 IC5.21 140.5,83.9 140.5,84.7 v141.5,85.7 | v142,94.2 143.9,94.2 145.2,95.5 J1.6
  Top 0.18: 140.5,83.8 140.5,81.25 141,80.75 142.75,80.75 v143.3,81.3
  Bottom 0.178: v143.3,81.3 144.8,79.8 144.8,78.8 R2.2A | v142,94.2 141.5,93.7 v141.5,85.7
N$8
  Top 0.18: SW1.COM R15.1
N$9  (via drill 0.51)
  Top 0.178: v143.3,85.3 143.3,85 143,84.7 143,83.9 IC5.16
  Bottom 0.178: R1.3B 140.9,78.8
  Bottom 0.18: 140.9,78.8 140.9,80.85 140.25,81.5 140.25,83 141,83.75 141.75,83.75 v143.3,85.3
N$10
  Top 0.18: SW2.COM R16.1
N$11  (via drill 0.51)
  Top 0.178: v146.4,82.5 146.4,83 146.5,83.1 146.5,83.8 IC5.9
  Bottom 0.178: v146.4,82.5 146.4,78.8 R2.4A
N$12  (via drill 0.51)
  Top 0.178: 142,83.8 IC5.18
  Top 0.18: 142,83.8 142,81.75 v141.75,81.5
  Bottom 0.178: R1.2B 141.7,78.8
  Bottom 0.18: 141.7,78.8 141.7,81.45 v141.75,81.5
N$13  (via drill 0.51)
  Top 0.178: v143.1,82.5 143.6,83 143.6,83.8 IC5.15
  Bottom 0.178: v143.1,82.5 142.5,81.9 142.5,78.8 R1.1B
N$14
  Top 0.18: IC7.3 48.98,25.18 R12.2 44.2,25.5 C42.POS 42.25,31.71 IC8.3
N$15
  Top 0.18: J2.CONDUCTOR 24,12.35 OSC1.OUT
N$16  (via drill 0.51)
  Top 0.178: v139.6,86.4 140.1,85.9 140.1,83.9 IC5.22 | v137.3,89.9 137.3,91.4 137,91.7 IC1.3
  Bottom 0.178: v139.6,86.4 139.6,87.6 v137.3,89.9
N$17
  Top 0.18: C43.1 5.95,36.95 6,37 6.85,37 OSC1.CTRL 13.25,42.9 13.25,76 2.73,86.52 R13.W
N$18
  Top 0.18: R13.CW 5.27,145.02 3.75,143.5 3.75,87.25 14.5,76.5 14.5,38.25 OSC1.VREF
N$19
  Top 0.18: OSC1.VDD 26.2,36.75 C46.1 C45.1 37.95,33.95 39,35 47,35 49.33,37.33 | 46.75,45.2 C44.POS 47.05,39.61 49.33,37.33 | 49.33,37.33 IC8.2
  pour Top: 46.25,43.25 46.25,27.25 79.25,27.25 79.25,43.25
N$20
  Top 0.18: OCXO+.TP 45.5,20.25 46.5,21.25 47.2,21.25 R9.2 50.2,21.2 50.75,21.75 50.75,22.39 IC7.1
N$21
  Top 0.18: J3.CONDUCTOR 116.5,134.45 R15.2 R18.2
N$22
  Top 0.18: R18.1 IC9.2
N$23
  Top 0.18: J4.CONDUCTOR 96.5,134.45 R16.2 R19.2
N$24
  Top 0.18: R19.1 IC10.2
N$25
  Top 0.18: J6.CONDUCTOR 56.5,134.45 R21.2
N$26
  Top 0.18: IC12.4 55.65,131.7 R21.1
N$27
  Top 0.18: J7.CONDUCTOR 36.5,134.45 R22.2
N$28
  Top 0.18: IC13.4 35.65,131.7 R22.1
N$29
  Top 0.18: IC3.1 137.71,39.24 R3.2
N$30  (via drill 0.51)
  Top 0.178: v172.8,112.4 170.8,110.4 170.8,108.5 MOD1.24 | v178,112.7 179.1,112.7 180.9,110.9 v185,110.9
  Bottom 0.178: v172.8,112.4 173.2,112.4 173.6,112 176,112 176.7,112.7 v178,112.7 | v185,110.9 185.2,110.9 187.8,108.3 | 187.8,96.5 186.7,95.4 183.9,95.4 183.3,96 183.3,97.2 DIS1.RXD
  Bottom 0.18: 187.8,108.3 187.8,105.7 189,104.5 189,97.7 187.8,96.5
N$31
  Top 0.18: 48.25,19.25 IC7.4 | 48.25,19.25 47.3,19.25 R9.1 | 48.25,19.25 R10.2 50.16,15.3 R11.2
N$32
  Top 0.18: IC4.1 151.71,39.24 R4.2
N$33
  Top 0.178: DDS1.P1.39 104.1,30.8 104.1,33.2 DDS1.P1.37 104,33.3 104,35.8 | 104,35.8 104,38.3 DDS1.P1.33 104.1,38.4 104.1,40.8 DDS1.P1.31 104,40.9 104,43.4 DDS1.P1.29 104,43.5 104,45.9 DDS1.P1.27 104,46 104,48.5 | 104,35.8 DDS1.P1.35 | 104,48.5 104,51 DDS1.P1.23 104,51.1 104,53.5 DDS1.P1.21 104,53.6 104,56.1 DDS1.P1.19 104,56.2 104,58.6 DDS1.P1.17 104,58.7 104,61.2 | 104,61.2 104,63.7 DDS1.P1.13 104,63.8 104,66.1 DDS1.P1.11 | DDS1.U6.17 95.4,71.7 95.4,69.2 DDS1.U6.19 95.4,69.1 95.8,69.1 98.9,66 100,66 | 100,66 103.8,66 104,66.2 DDS1.P1.11 | DDS1.P1.9 104,68.8 104,66.3 DDS1.P1.11 | 100,66 R14.1 | 104,61.2 DDS1.P1.15 | 104,48.5 DDS1.P1.25
N$34
  Top 0.18: SW3.COM R17.1
N$35
  Top 0.18: J5.CONDUCTOR 76,137.8 R17.2 R20.2
N$36
  Top 0.18: R20.1 IC11.2
N$37
  Top 0.18: J8.CONDUCTOR 16.5,134.45 R23.2
N$38
  Top 0.18: IC14.4 15.65,131.7 R23.1
N$39
  Top 0.18: 0.09,2.09 0.09,0.09 2.09,0.09
N$40
  Bottom 0.18: 0.09,2.09 0.09,0.09 2.09,0.09
N$41
  Bottom 0.18: 191.41,2.09 191.41,0.09 189.41,0.09
N$42
  Top 0.18: 59.25,117.05 R7.2 | 59.25,117.05 C37.1 | IC6.1 59.29,117.01 59.25,117.05
N$43
  Top 0.18: 191.41,2.09 191.41,0.09 189.41,0.09
N$44
  Top 0.18: 189.41,151.16 191.41,151.16 191.41,149.16
N$45
  Bottom 0.18: 189.41,151.16 191.41,151.16 191.41,149.16
N$46
  Bottom 0.18: 2.09,151.16 0.09,151.16 0.09,149.16
N$47
  Top 0.18: 2.09,151.16 0.09,151.16 0.09,149.16
N$62
  Top 0.178: TP1.TP 156.9,59.1 154.7,59.1 151.7,62.1 151.7,66 152.2,66.5 153,66.5 IC5.114
N$66  (via drill 0.51)
  Top 0.178: v154.5,65.4 153.9,66 153.1,66 IC5.113
  Bottom 0.178: v154.5,65.4 154.5,62.4 155.8,61.1 156.9,61.1 TP2.TP
OUT1  (via drill 0.51)
  Top 0.178: IC12.2 55,126.2 v65.9,115.3 | 117.9,75.7 v117.9,73.8 | v128.7,63 132.3,63 133.6,64.3 134.2,64.3 134.9,63.6 134.9,63 135,62.9 135,62.1 IC5.77
  Top 0.18: v106.3,87.3 106.7,87.3 108.75,85.25 108.75,84.85 117.9,75.7
  Bottom 0.178: v65.9,115.3 76.9,115.3 97.2,95 98.6,95 v106.3,87.3 | v117.9,73.8 v128.7,63
OUT2  (via drill 0.51)
  Top 0.178: v35,121.2 IC13.2 | v136.3,60.7 136.3,61.1 136.1,61.3 136.1,62 IC5.79
  Bottom 0.178: v35,121.2 93.9,62.3 122.8,62.3 123.6,61.5
  Bottom 0.18: 123.6,61.5 129.5,61.5 130.25,62.25 135,62.25 136.3,60.95 v136.3,60.7
OUT3  (via drill 0.51)
  Top 0.178: IC14.2 15,126.2 v19.2,122 | v136.3,64.3 136.3,63.1 136.6,62.8 136.6,62.1 IC5.80
  Top 0.18: v123.1,75.4 122.6,75.4 110.5,87.5 109.4,87.5 v109.2,87.7
  Bottom 0.178: v123.1,75.4 123.1,73.5 130.7,65.9 134.7,65.9 v136.3,64.3
  Bottom 0.18: v19.2,122 26,122 28,124 72.9,124 99,97.9 99,96.5 102,93.5 103.5,93.5 109.2,87.8 v109.2,87.7
P0  (via drill 0.51)
  Top 0.178: v133.3,72.7 132.9,73.1 131.4,73.1 IC5.54 | v119,73.8 v123.9,73.8 | v109.1,79.8 108.6,79.8 102.6,85.8 96.7,85.8 95.6,86.9 95.4,86.9 DDS1.U6.5
  Bottom 0.178: v133.3,72.7 133.3,72 130.3,69 128.7,69 v123.9,73.8 | v119,73.8 113,79.8 v109.1,79.8
P1
  Top 0.178: IC5.53 131.3,73.5 130.5,73.5 130.3,73.3 124.5,73.3 124.2,73 114.8,73 104.5,83.3 96.6,83.3 95.4,84.5 DDS1.U6.7
P2  (via drill 0.51)
  Top 0.178: v115.4,81.4 122.2,74.6 124.2,74.6 124.8,74 131.3,74 IC5.52
  Bottom 0.178: v115.4,81.4 99.6,81.4 98.7,80.5 96.6,80.5 95.3,81.8 DDS1.U6.9
PLL_LOCK  (via drill 0.51)
  Top 0.178: v136.3,68.6 132.4,72.5 131.4,72.5 IC5.55 | v146.9,24.5 146.9,18.1 147,18 DDS1.U9.15
  Bottom 0.178: 146.9,54.8 138.3,63.4
  Bottom 0.18: v136.3,68.6 136.3,67.7 137.25,66.75 137.25,64.45 138.3,63.4 | 146.9,54.8 148,53.7 148,26 146.9,24.9 v146.9,24.5
RAM_SWP_OVR  (via drill 0.51)
  Top 0.178: v134.5,65 134.5,68.7 132.2,71 131.4,71 IC5.58 | v142.2,29.2 142.2,18.1 142.1,18 DDS1.U9.19
  Bottom 0.178: 134.5,64.85 v134.5,65 | v142.2,29.2 142.2,56.9
  Bottom 0.18: 134.5,64.85 136.6,62.75 137.5,62.75 142.2,58.05 142.2,56.9
RESET  (via drill 0.51)
  Top 0.178: v133.3,65.1 133.3,68.9 132.2,70 131.4,70 IC5.60
  Bottom 0.178: v133.3,65.1 134.2,64.2 134.55,64.2 | 141,29.3 141,57.5
  Bottom 0.18: 134.55,64.2 136.5,62.25 137.25,62.25 141,58.5 141,57.5 | 141,29.3 141,25.5 144.5,22 148.1,22 DDS1.U9.11
SCLK  (via drill 0.51)
  Top 0.178: v129.6,75.2 129.9,75.5 131.3,75.5 IC5.49 | v80.8,83.3 70.1,94 69.9,94 DDS1.U5.5
  Bottom 0.178: v129.6,75.2 129.2,75.2 121.6,82.8
  Bottom 0.18: v80.8,83.3 107.7,83.3 108,83 121.4,83 121.6,82.8
SDIO  (via drill 0.51)
  Top 0.178: v129.3,78.3 129.6,78 131.3,78 IC5.44 | v83.3,85.8 75,94.1 DDS1.U5.9
  Bottom 0.178: v129.3,78.3 126.9,78.3 121.6,83.6 | 100.4,84.1 98.7,85.8 v83.3,85.8
  Bottom 0.18: 100.4,84.1 100.75,83.75 108.5,83.75 108.65,83.6 121.6,83.6
SDO  (via drill 0.51)
  Top 0.178: v123.9,76.8 128.3,76.8 128.6,77.1 131.3,77.1 IC5.46 | v115.9,79.8 110.6,85.1 110.6,85.2 99.8,96 v94.4,96
  Bottom 0.178: v123.9,76.8 120.9,79.8 v115.9,79.8 | v94.4,96 90.1,91.7 74.8,91.7 72.4,94.1 DDS1.U5.7
SP0  (via drill 0.51)
  Top 0.178: 132.1,82.9 134.35,80.65 134.35,77.45 137.1,74.7 137.1,72.9 138.1,71.9 138.1,62.1 IC5.83 | v156.4,116.2 v161.3,121.1 | v173.9,112.8 173.9,111.9 172.1,110.1 172.1,108.5 MOD1.22
  Top 0.18: v132.1,88 132.1,87.85 131.5,87.25 131.5,83.5 132.1,82.9
  Bottom 0.178: v132.1,88 132.1,91.9 v156.4,116.2 | v161.3,121.1 165.6,121.1 v173.9,112.8
SP1  (via drill 0.51)
  Top 0.178: v139.05,64.3 138.6,63.85 138.6,62.1 IC5.84 | v170.4,93.5 170.4,106.8 170.7,107.1 MOD1.23
  Bottom 0.178: 142.7,64.3 v139.05,64.3 | 153.7,75.55 153.7,76.8 v170.4,93.5
  Bottom 0.18: 142.7,64.3 148.65,70.25 149.25,70.25 150.25,71.25 150.25,72 153.7,75.45 153.7,75.55
SP2  (via drill 0.51)
  Top 0.178: v142.1,60.7 139.6,60.7 139.1,61.2 139.1,62 IC5.85 | v147.5,67.8 147.5,67 v148.2,66.3 | v178.7,95.7 178.7,98 181.5,100.8 186,100.8 189.9,104.7 189.9,108.4 181.9,116.4 172.1,116.4 165.7,110 165.7,108.5 MOD1.32
  Bottom 0.178: v148.2,66.3 150.9,69 150.9,69.1 154.3,72.5 155.5,72.5 v178.7,95.7
  Bottom 0.18: v142.1,60.7 142.1,62.85 146.75,67.5 147.2,67.5 v147.5,67.8
SP3  (via drill 0.51)
  Top 0.178: v139,81.4 139,65.9 | v157.5,116.2 157.5,116.7 160.8,120 164.2,120 166.8,117.4 166.8,113.1 163.2,109.5 163.2,108.5 MOD1.36
  Top 0.18: IC5.86 139.54,63.29 140,63.75 140,64.9 139,65.9
  Bottom 0.178: v139,81.4 139,84.7 140.4,86.1 140.4,90.4 138.7,92.1 138.7,97.4
  Bottom 0.18: v157.5,116.2 156.55,115.25 156,115.25 138.7,97.95 138.7,97.4
TX_EN  (via drill 0.51)
  Top 0.178: v129.4,71.3 130.1,70.6 131.3,70.6 IC5.59
  Bottom 0.178: 101.3,80.6 98.6,77.9 96.6,77.9 95.4,76.7 DDS1.U6.13
  Bottom 0.18: v129.4,71.3 128.7,71.3 124.75,75.25 124.75,77.05 121.2,80.6 114.9,80.6 114.5,81 101.7,81 101.3,80.6

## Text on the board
Top: 1 2 | General Purpose DDS Rev:A University of Toronto J. Thywissen Labs
tDocu: General Purpose DDS | A. Stummer May'11 | A1 | 0.18mm | 0.18mm | 0.36mm | 0.1mm | 0.25mm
